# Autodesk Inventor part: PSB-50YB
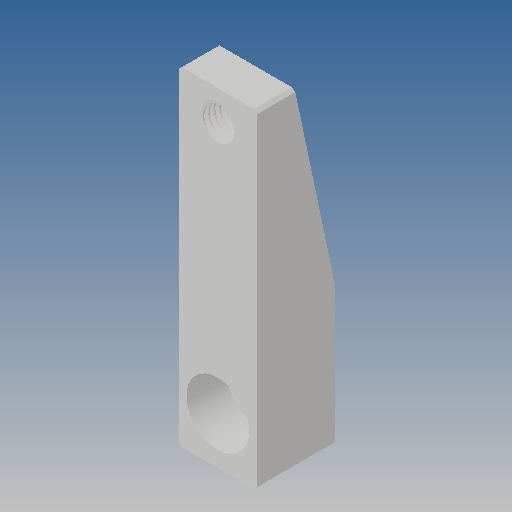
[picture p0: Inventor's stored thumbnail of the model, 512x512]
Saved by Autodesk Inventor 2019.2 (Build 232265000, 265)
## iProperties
Created: 2010-02
Part Number: PSB-50YB
Material: Ogólny
Document SubType Name: Modeling
Designer: CADENGINEERING4
Density: 1 g/cm^3
Appearance: Domyślna
Author: CADENGINEERING4
Revision Number: 1LAST_VERSION
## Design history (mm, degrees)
feature "Baza1"
node "Bryła1"
